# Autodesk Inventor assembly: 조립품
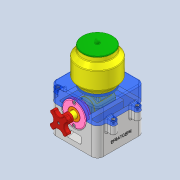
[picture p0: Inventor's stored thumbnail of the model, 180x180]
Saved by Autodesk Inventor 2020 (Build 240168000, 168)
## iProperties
Created: 2022-03
Part Number: 조립품
Document SubType Name: Assembly
Designer: Administrator
Author: Administrator
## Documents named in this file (11)
- C:\Users\Administrator\Desktop\720306V1016\조립품.iam
- C:\Users\Administrator\Desktop\720306V1016\본체.ipt
- C:\Users\Administrator\Desktop\720306V1016\본체커버.ipt
- C:\Users\Administrator\Desktop\720306V1016\핸들축.ipt
- C:\Users\Administrator\Desktop\720306V1016\용기.ipt
- C:\Users\Administrator\Desktop\720306V1016\용기캡.ipt
- C:\Users\Administrator\Desktop\720306V1016\앞커버.ipt
- C:\Users\Administrator\Desktop\720306V1016\베어링 부시.ipt
- C:\Users\Administrator\Desktop\720306V1016\핸들.ipt
- C:\Users\Administrator\Desktop\720306V1016\볼트 M3x12.ipt
- C:\Users\Administrator\Desktop\720306V1016\볼트 M4x12.ipt
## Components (2 placed, 2 different names)
1. 핸들축:1
2. 핸들:1
